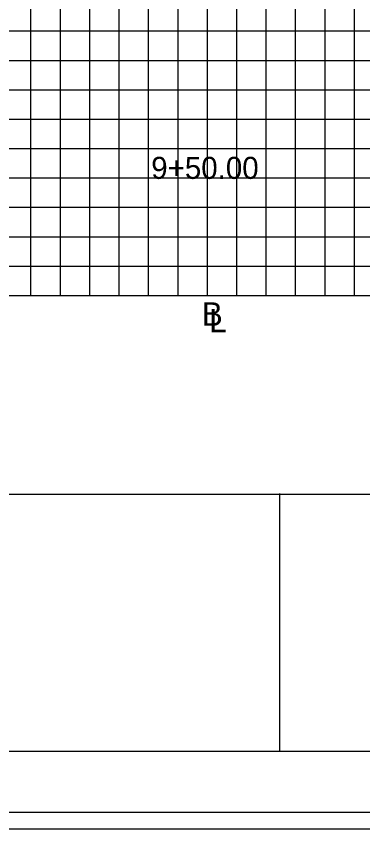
# Model space of a CAD drawing. Extents: x 967 to 1326, y 964 to 3144.
# Drawn here: x 1147 to 1170.6, y 1243.7 to 1299 of the extents above; entities that cross this region are included whole.
import ezdxf

# ---------------------------------------------------------------- set-up
doc = ezdxf.new("R2010")
doc.units = 0
for name, color, linetype in [('Default', 7, 'Continuous'), ('RD_SHT_Bndy', 7, 'Continuous'), ('RD_SHT_IplotShp', 7, 'Continuous'), ('RD_SHT_MjGrid', 7, 'Continuous'), ('RD_SHT_MnGrid', 7, 'Continuous'), ('RD_SHT_TX', 7, 'Continuous'), ('RD_Sketch1', 7, 'Continuous')]:
    doc.layers.add(name, color=color, linetype=linetype)

msp = doc.modelspace()

# ---------------------------------------------------------------- linework, layer by layer
at = {"layer": 'RD_SHT_Bndy'}
for p, q in [((996.114, 1266.486), (1323.886, 1266.486)), ((1164.932, 1248.983), (1164.932, 1266.526)), ((1323.886, 1248.983), (996.114, 1248.983))]:
    msp.add_line(p, q, dxfattribs=at)
at = {"layer": 'RD_SHT_IplotShp'}
for points in [[(967.409, 1243.72), (1326.285, 1243.72), (1326.285, 1463.72), (967.409, 1463.72)], [(988.525, 1244.84), (1326.285, 1244.84), (1326.285, 1462.6), (988.525, 1462.6)]]:
    msp.add_lwpolyline(points, close=True, dxfattribs=at)
at = {"layer": 'RD_SHT_MjGrid'}
for p, q in [((1150, 1280), (1150, 1450)), ((1160, 1280), (1160, 1450)), ((1170, 1280), (1170, 1450)), ((1000, 1290), (1320, 1290)), ((1000, 1280), (1320, 1280))]:
    msp.add_line(p, q, dxfattribs=at)
at = {"layer": 'RD_SHT_MnGrid'}
for p, q in [((1148, 1280), (1148, 1450)), ((1152, 1280), (1152, 1450)), ((1154, 1280), (1154, 1450)), ((1156, 1280), (1156, 1450)), ((1158, 1280), (1158, 1450)), ((1162, 1280), (1162, 1450)), ((1164, 1280), (1164, 1450)), ((1166, 1280), (1166, 1450)), ((1168, 1280), (1168, 1450)), ((1000, 1298), (1320, 1298)), ((1000, 1296), (1320, 1296)), ((1000, 1294), (1320, 1294)), ((1000, 1292), (1320, 1292)), ((1000, 1288), (1320, 1288)), ((1000, 1286), (1320, 1286)), ((1000, 1284), (1320, 1284)), ((1000, 1282), (1320, 1282))]:
    msp.add_line(p, q, dxfattribs=at)
at = {"layer": 'RD_Sketch1'}
msp.add_lwpolyline([(967.409, 1243.72), (1326.285, 1243.72), (1326.285, 1463.72), (967.409, 1463.72)], close=True, dxfattribs=at)

# ---------------------------------------------------------------- texts
at = {"layer": 'Default'}
msp.add_text('9+50.00', height=1.5, dxfattribs=at).set_placement((1156.179, 1287.935))
at = {"layer": 'RD_SHT_TX'}
for s, p in [('B', (1159.615, 1277.941)), ('L', (1160.124, 1277.491))]:
    msp.add_text(s, height=1.6, dxfattribs=at).set_placement(p)

doc.saveas('drawing.dxf')
